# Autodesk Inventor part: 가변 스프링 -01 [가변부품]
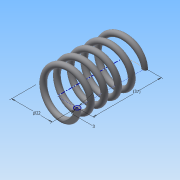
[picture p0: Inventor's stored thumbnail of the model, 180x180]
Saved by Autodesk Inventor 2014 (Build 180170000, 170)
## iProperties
Created: 2015-09
Part Number: 가변 스프링 -01 [가변부품]
Material: 강철, 탄소
Document SubType Name: Modeling
Designer: study
Density: 7.87 g/cm^3
Appearance: 반연마
Mass: 18.8544 g
Surface Area: 32.5077 cm^2
Volume: 2.39574 cm^3
Author: study
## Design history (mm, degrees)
sketch "스케치1"
  geometry: L1 (0, 0)-(11, 0); L2 (11, 0)-(11, 39.945); L3 (11, 39.945)-(0, 39.945); L4 (0, 39.945)-(0, 0); C1 r 1.5 at (11, 0)
  constraints: 8 end point, 2 parallel, 1 centre point, 1 coincident, 1 horizontal, 1 perpendicular
  dimensions: "d0" = 3 diameter of C1; "d1" = 22 diameter of L2 L4; "d2" = 39.9455 distance of L1.end L2.end (derived)
feature "코일1" pitch "d3" = 10; turns "d5" = 5; dims "d4" = 39.9455 (= d2), "d6" = 0, angle "d7" = 90 deg, angle "d8" = 90 deg, "d9" = 0, "d10" = 0
node "작업 평면1"
sketch "스케치2"
  geometry: L1 (-12.5, 0)-(-9.5, 0) reference; L2 (-12.5, 0)-(-9.5, 0) reference; 1 further point
  constraints: 2 horizontal alignment
extrude "돌출1" cut sketch "스케치2" stored distance "d12" = 10; taper "d13" = 0 deg
node "작업 평면2"
sketch "스케치3"
  geometry: L1 (-9.5, 0)-(-12.5, 0) reference; 1 further point
  constraints: 1 horizontal alignment
extrude "돌출2" cut sketch "스케치3" stored distance "d15" = 10; taper "d16" = 0 deg
node "솔리드1"
node "절단 모서리 투영1"
node "절단 모서리 투영2"
node "절단 모서리 투영3"
other parameters: "d11" = 0, "d14" = 39.9455 (= d2)
